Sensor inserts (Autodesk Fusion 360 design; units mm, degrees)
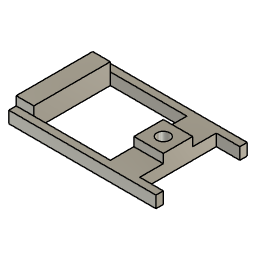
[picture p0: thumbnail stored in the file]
base_mesh_feature "Base Mesh Feature1"
convert_mesh "Convert Mesh1" bodies "DHT22_Case_-_DHT22_Case_Bot"
sketch "Sketch1" plane through (0, 0, 2) normal (0, 0, 1) x axis (-1, 0, 0)
  line L1 (18.25, 7.75) -> (18.25, -7.75)
  line L2 (18.25, -7.75) -> (-18.25, -7.75)
  line L3 (-18.25, -7.75) -> (18.25, -7.75)
  line L4 (-18.25, 7.75) -> (-18.25, -7.75)
  line L5 (18.25, 7.75) -> (-18.25, 7.75)
  line L6 (18.25, -7.75) -> (18.25, 7.75)
  line L7 (18.25, -6.5) -> (-18.25, -6.5)
  line L8 (-18.25, 6.5) -> (18.25, 6.5)
  line L9 (6.75, 7.75) -> (6.75, -7.75)
  line L10 (-14.25, 6.5) -> (-14.25, -6.5)
  line L11 (-9.25, -6.5) -> (-14.25, -6.5)
  line L12 (-9.25, 6.5) -> (-9.25, -6.5)
  line L13 (-14.25, 6.5) -> (-9.25, 6.5)
  line L14 (-14.25, -6.5) -> (-14.25, 6.5)
  line L15 (3.75, -6.5) -> (6.75, -6.5)
  line L16 (3.75, 6.5) -> (3.75, -6.5)
  line L17 (6.75, 6.5) -> (3.75, 6.5)
  line L18 (6.75, -6.5) -> (6.75, 6.5)
  line L19 (-14.25, -7.75) -> (6.75, -7.75)
  line L20 (6.75, -6.5) -> (-14.25, -6.5)
  line L21 (6.75, -7.75) -> (6.75, -6.5)
  line L22 (-14.25, 6.5) -> (6.75, 6.5)
  line L23 (6.75, 7.75) -> (-14.25, 7.75)
  line L24 (6.75, 6.5) -> (6.75, 7.75)
  line L25 (-18.25, -7.75) -> (-14.25, -7.75)
  line L26 (-18.25, -6.5) -> (-18.25, -7.75)
  line L27 (-14.25, -6.5) -> (-18.25, -6.5)
  line L28 (-18.25, 6.5) -> (-14.25, 6.5)
  line L29 (-18.25, 7.75) -> (-18.25, 6.5)
  line L30 (-14.25, 7.75) -> (-18.25, 7.75)
  point P2 (18.25, -7.75)
  point P5 (18.25, -7.75)
  point P9 (-18.25, -6.5)
  point P10 (18.25, -6.5)
  point P11 (18.25, 6.5)
  point P12 (-18.25, 6.5)
  point P13 (6.75, -7.75)
  point P14 (6.75, 7.75)
  point P15 (-14.25, -6.5)
  point P16 (-14.25, 6.5)
  point P20 (6.75, -6.5)
  point P27 (-14.25, 7.75)
  point P6 (-18.25, -7.75)
  point P8 (18.25, 7.75)
  point P4 (-18.25, -7.75)
  point P17 (-9.25, -6.5)
  point P21 (3.75, -6.5)
  horizontal L3
  vertical L4
  horizontal L5
  vertical L6
  coincident P2 P5
  coincident L4 P9
  coincident L6 P10
  perpendicular L6 L7
  coincident L6 P11
  coincident L4 P12
  perpendicular L4 L8
  coincident L3 P13
  coincident L5 P14
  perpendicular L5 L9
  coincident L7 P15
  coincident L8 P16
  perpendicular L8 L10
  horizontal L11
  vertical L12
  horizontal L13
  vertical L14
  horizontal L15
  vertical L16
  horizontal L17
  vertical L18
  coincident L9 P20
  coincident L7 P20
  horizontal L19
  horizontal L20
  vertical L21
  horizontal L22
  horizontal L23
  vertical L24
  coincident L5 P27
  horizontal L25
  vertical L26
  horizontal L27
  horizontal L28
  vertical L29
  horizontal L30
  dimension "d1" distance P5 P6 = 36.5
  dimension "d2" distance P5 P8 = 15.5
  dimension "d5" distance P4 L7 = 1.25
  dimension "d6" distance L5 L8 = 1.25
  dimension "d7" distance L6 L9 = 11.5 (= "36.5 mm - 25 mm")
  dimension "d8" distance L4 L10 = 4
  dimension "d9" distance P15 P17 = 5
  dimension "d10" distance P20 P21 = 3
extrude "Extrude1" new body sketch "Sketch1" profile of L2 L3 L5 L11 L13 L15 L17 L19 L20 L21 L22 L23 L24 along normal blind 2
extrude "Extrude2" add sketch "Sketch1" profile of L11 L12 L13 L14 L15 L16 L17 L18 L20 L22 along normal blind 3.5
sketch "Sketch2" plane through (0, 0, 5.5) normal (0, 0, 1) x axis (-1, 0, 0)
  line L1 (-9.25, 6.5) -> (-9.25, -6.5)
  line L2 (-14.25, 6.5) -> (-9.25, 6.5)
  line L3 (-14.25, -6.5) -> (-14.25, 6.5)
  line L4 (-9.25, -6.5) -> (-14.25, -6.5)
  line L5 (-14.25, 6.5) -> (-9.25, -6.5)
  line L6 (-9.25, 6.5) -> (-14.25, -6.5)
  line L7 (-9.25, -2.5) -> (-14.25, -2.5)
  line L8 (-9.25, 2.5) -> (-9.25, -2.5)
  line L9 (-14.25, 2.5) -> (-9.25, 2.5)
  line L10 (-14.25, -2.5) -> (-14.25, 2.5)
  circle C1 centre (-11.75, 0) radius 1
  point P2 (-9.25, -6.5)
  point P6 (-9.25, -6.5)
  point P4 (-14.25, 6.5)
  point P7 (-14.25, 6.5)
  point P5 (-14.25, -6.5)
  point P8 (-14.25, -6.5)
  point P3 (-9.25, 6.5)
  point P9 (-9.25, 6.5)
  point P10 (-11.75, 0)
  point P11 (-14.25, -2.5)
  point P14 (-14.25, 2.5)
  coincident P2 P6
  coincident P4 P7
  coincident P5 P8
  coincident P3 P9
  midpoint L6 P10
  horizontal L7
  vertical L8
  horizontal L9
  vertical L10
  dimension "d15" diameter C1 = 2
  dimension "d55" distance P11 P14 = 5
hole "Hole1" HoleDepth 4 HoleDiameter 2.2 TipAngle 180
base_mesh_feature "Base Mesh Feature2"
convert_mesh "Convert Mesh2" bodies "MQ2_Case_-_MQ2_Case_Bot"
sketch "Sketch3" plane through (0, 0, 0) normal (0, 0, 1) x axis (1, 0, 0)
  line L1 (17, -42) -> (-17, -42)
  line L2 (17, -64) -> (17, -42)
  line L3 (-17, -64) -> (17, -64)
  line L4 (-17, -42) -> (-17, -64)
  line L5 (17, -43.5) -> (-17, -43.5)
  line L6 (17, -62.5) -> (-17, -62.5)
  line L7 (-14, -64) -> (-14, -42)
  line L8 (12, -43.5) -> (17, -43.5)
  line L9 (12, -47.5) -> (12, -43.5)
  line L10 (17, -47.5) -> (12, -47.5)
  line L11 (17, -43.5) -> (17, -47.5)
  line L12 (12, -62.5) -> (17, -62.5)
  line L13 (12, -58.5) -> (12, -62.5)
  line L14 (17, -58.5) -> (12, -58.5)
  line L15 (17, -62.5) -> (17, -58.5)
  line L16 (-9, -43.5) -> (-14, -43.5)
  line L17 (-9, -47.5) -> (-9, -43.5)
  line L18 (-14, -47.5) -> (-9, -47.5)
  line L19 (-14, -43.5) -> (-14, -47.5)
  line L20 (17, -42) -> (-14, -42)
  line L21 (17, -43.5) -> (17, -42)
  line L22 (-14, -43.5) -> (17, -43.5)
  line L23 (-14, -42) -> (-14, -43.5)
  line L24 (-9, -62.5) -> (-14, -62.5)
  line L25 (-9, -58.5) -> (-9, -62.5)
  line L26 (-14, -58.5) -> (-9, -58.5)
  line L27 (-14, -62.5) -> (-14, -58.5)
  line L28 (-14, -64) -> (17, -64)
  line L29 (-14, -62.5) -> (-14, -64)
  line L30 (17, -62.5) -> (-14, -62.5)
  line L31 (17, -64) -> (17, -62.5)
  line L32 (-12.5, -47.5) -> (-14, -47.5)
  line L33 (-12.5, -58.5) -> (-12.5, -47.5)
  line L34 (-14, -58.5) -> (-12.5, -58.5)
  line L35 (-14, -47.5) -> (-14, -58.5)
  line L36 (15.5, -47.5) -> (17, -47.5)
  line L37 (15.5, -58.5) -> (15.5, -47.5)
  line L38 (17, -58.5) -> (15.5, -58.5)
  line L39 (17, -47.5) -> (17, -58.5)
  point P6 (-17, -43.5)
  point P7 (17, -43.5)
  point P8 (-17, -62.5)
  point P9 (17, -62.5)
  point P10 (-14, -42)
  point P11 (-14, -64)
  point P18 (-14, -43.5)
  point P24 (-14, -62.5)
  point P31 (-12.5, -58.5)
  point P34 (15.5, -58.5)
  point P12 (12, -43.5)
  point P14 (17, -47.5)
  point P15 (12, -62.5)
  point P17 (17, -58.5)
  point P19 (-9, -43.5)
  point P21 (-14, -47.5)
  point P25 (-9, -62.5)
  point P27 (-14, -58.5)
  horizontal L1
  vertical L2
  horizontal L3
  vertical L4
  coincident L4 P6
  coincident L2 P7
  perpendicular L2 L5
  coincident L4 P8
  coincident L2 P9
  perpendicular L4 L6
  coincident L1 P10
  coincident L3 P11
  perpendicular L3 L7
  horizontal L8
  vertical L9
  horizontal L10
  vertical L11
  horizontal L12
  vertical L13
  horizontal L14
  vertical L15
  horizontal L16
  vertical L17
  horizontal L18
  vertical L19
  coincident L5 P18
  coincident L7 P18
  horizontal L20
  vertical L21
  horizontal L22
  vertical L23
  horizontal L24
  vertical L25
  horizontal L26
  vertical L27
  coincident L7 P24
  coincident L6 P24
  horizontal L28
  vertical L29
  horizontal L30
  vertical L31
  horizontal L32
  vertical L33
  horizontal L34
  vertical L35
  coincident L26 P31
  horizontal L36
  vertical L37
  horizontal L38
  vertical L39
  coincident L14 P34
  dimension "d19" distance L1 L5 = 1.5
  dimension "d20" distance L3 L6 = 1.5
  dimension "d21" distance L4 L7 = 3
  dimension "d22" distance P7 P12 = 5
  dimension "d23" distance P7 P14 = 4
  dimension "d24" distance P9 P15 = 5
  dimension "d25" distance P9 P17 = 4
  dimension "d26" distance P18 P19 = 5
  dimension "d27" distance P18 P21 = 4
  dimension "d28" distance P24 P25 = 5
  dimension "d29" distance P24 P27 = 4
extrude "Extrude1" new body sketch "Sketch3" profile of L1 L2 L3 L8 L10 L12 L14 L16 L18 L20 L21 L22 L23 L24 L26 L28 L29 L30 L31 L32 L33 L34 L35 L36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 along normal blind 2
extrude "Extrude2" add sketch "Sketch3" profile of L2 L8 L9 L10 L11 L12 L13 L14 L15 L16 L17 L18 L19 L22 L24 L25 L26 L27 L30 L32 L34 L36 L38 along normal blind 6
sketch "Sketch4" plane through (0, 0, 6) normal (0, 0, 1) x axis (-1, 0, 0)
  line L1 (14, 43.5) -> (9, 43.5)
  line L2 (14, 47.5) -> (14, 43.5)
  line L3 (9, 47.5) -> (14, 47.5)
  line L4 (9, 43.5) -> (9, 47.5)
  line L5 (10, 43.5) -> (14, 43.5)
  line L6 (10, 47.5) -> (10, 43.5)
  line L7 (14, 47.5) -> (10, 47.5)
  line L8 (14, 43.5) -> (14, 47.5)
  line L9 (10, 58.5) -> (14, 58.5)
  line L10 (10, 62.5) -> (10, 58.5)
  line L11 (14, 62.5) -> (10, 62.5)
  line L12 (14, 58.5) -> (14, 62.5)
  line L13 (-13, 43.5) -> (-17, 43.5)
  line L14 (-13, 47.5) -> (-13, 43.5)
  line L15 (-17, 47.5) -> (-13, 47.5)
  line L16 (-17, 43.5) -> (-17, 47.5)
  line L17 (-13, 58.5) -> (-17, 58.5)
  line L18 (-13, 62.5) -> (-13, 58.5)
  line L19 (-17, 62.5) -> (-13, 62.5)
  line L20 (-17, 58.5) -> (-17, 62.5)
  line L21 (10, 47.5) -> (14, 43.5)
  line L22 (10, 43.5) -> (14, 47.5)
  line L23 (-17, 47.5) -> (-13, 43.5)
  line L24 (-17, 43.5) -> (-13, 47.5)
  line L25 (-17, 62.5) -> (-13, 58.5)
  line L26 (-17, 58.5) -> (-13, 62.5)
  line L27 (10, 62.5) -> (14, 58.5)
  line L28 (10, 58.5) -> (14, 62.5)
  circle C1 centre (12, 45.5) radius 1
  circle C2 centre (-15, 45.5) radius 1
  circle C3 centre (12, 60.5) radius 1
  circle C4 centre (-15, 60.5) radius 1
  point P8 (10, 47.5)
  point P3 (14, 43.5)
  point P6 (14, 43.5)
  point P22 (12, 45.5)
  point P23 (-15, 45.5)
  point P24 (12, 60.5)
  point P25 (-15, 60.5)
  horizontal L5
  vertical L6
  horizontal L7
  vertical L8
  coincident L3 P8
  coincident P3 P6
  horizontal L9
  vertical L10
  horizontal L11
  vertical L12
  horizontal L13
  vertical L14
  horizontal L15
  vertical L16
  horizontal L17
  vertical L18
  horizontal L19
  vertical L20
  perpendicular L23 L24
  perpendicular L24 L25
  perpendicular L26 L27
  midpoint L21 P22
  midpoint L23 P23
  midpoint L28 P24
  midpoint L26 P25
  dimension "d35" diameter C1 = 2
  dimension "d36" diameter C2 = 2
  dimension "d37" diameter C3 = 2
  dimension "d38" diameter C4 = 2
hole "Hole1" HoleDepth 4.5 HoleDiameter 2.2 TipAngle 180
sketch "Sketch1" plane through (0, 0, 2) normal (0, 0, 1) x axis (-1, 0, 0)
  line L1 (18.25, 7.75) -> (18.25, -7.75)
  line L2 (18.25, -7.75) -> (-18.25, -7.75)
  line L3 (-18.25, -7.75) -> (18.25, -7.75)
  line L4 (-18.25, 5.25) -> (-18.25, -7.75)
  line L5 (18.25, 5.25) -> (-18.25, 5.25)
  line L6 (18.25, -7.75) -> (18.25, 5.25)
  line L7 (18.25, -6.5) -> (-18.25, -6.5)
  line L8 (-18.25, 4) -> (18.25, 4)
  line L9 (6.75, 5.25) -> (6.75, -7.75)
  line L10 (-14.25, 4) -> (-14.25, -6.5)
  line L11 (-14.25, -7.75) -> (6.75, -7.75)
  line L12 (-14.25, -6.5) -> (-14.25, -7.75)
  line L13 (6.75, -6.5) -> (-14.25, -6.5)
  line L14 (6.75, -7.75) -> (6.75, -6.5)
  line L15 (6.75, 5.25) -> (-14.25, 5.25)
  line L16 (6.75, 6.5) -> (6.75, 5.25)
  line L17 (-18.25, -7.75) -> (6.75, -7.75)
  line L18 (-18.25, -10.25) -> (-18.25, -7.75)
  line L19 (6.75, -10.25) -> (-18.25, -10.25)
  line L20 (6.75, -7.75) -> (6.75, -10.25)
  line L21 (-18.25, 5.25) -> (6.75, 5.25)
  line L22 (-18.25, 7.75) -> (-18.25, 5.25)
  line L23 (6.75, 7.75) -> (-18.25, 7.75)
  line L24 (6.75, 5.25) -> (6.75, 7.75)
  line L25 (-9.25, -7.75) -> (-14.25, -7.75)
  line L26 (-9.25, 5.25) -> (-9.25, -7.75)
  line L27 (-14.25, 5.25) -> (-9.25, 5.25)
  line L28 (-14.25, -7.75) -> (-14.25, 5.25)
  line L29 (3.75, -7.75) -> (6.75, -7.75)
  line L30 (3.75, 5.25) -> (3.75, -7.75)
  line L31 (6.75, 5.25) -> (3.75, 5.25)
  line L32 (6.75, -7.75) -> (6.75, 5.25)
  point P2 (18.25, -7.75)
  point P5 (18.25, -7.75)
  point P9 (-18.25, -6.5)
  point P10 (18.25, -6.5)
  point P11 (18.25, 4)
  point P12 (-18.25, 4)
  point P13 (6.75, -7.75)
  point P14 (6.75, 5.25)
  point P15 (-14.25, -6.5)
  point P16 (-14.25, 4)
  point P20 (-14.25, 5.25)
  point P31 (3.75, 5.25)
  point P6 (-18.25, -7.75)
  point P8 (18.25, 5.25)
  point P4 (-18.25, -7.75)
  point P24 (6.75, -10.25)
  point P27 (6.75, 7.75)
  point P18 (-14.25, -7.75)
  point P28 (-9.25, -7.75)
  point P30 (3.75, -7.75)
  horizontal L3
  vertical L4
  horizontal L5
  vertical L6
  coincident P2 P5
  coincident L4 P9
  coincident L6 P10
  perpendicular L6 L7
  coincident L6 P11
  coincident L4 P12
  perpendicular L4 L8
  coincident L3 P13
  coincident L5 P14
  perpendicular L5 L9
  coincident L7 P15
  coincident L8 P16
  perpendicular L8 L10
  horizontal L11
  vertical L12
  horizontal L13
  vertical L14
  horizontal L15
  vertical L16
  coincident L5 P20
  horizontal L17
  vertical L18
  horizontal L19
  vertical L20
  horizontal L21
  vertical L22
  horizontal L23
  vertical L24
  horizontal L25
  vertical L26
  horizontal L27
  vertical L28
  horizontal L29
  vertical L30
  horizontal L31
  vertical L32
  coincident L15 P31
  dimension "d1_1" distance P5 P6 = 36.5
  dimension "d2_1" distance P5 P8 = 13
  dimension "d5_1" distance P4 L7 = 1.25
  dimension "d6_1" distance L5 L8 = 1.25
  dimension "d7_1" distance L6 L9 = 11.5 (= "36.5 mm - 25 mm")
  dimension "d8_1" distance L4 L10 = 4
  dimension "d42" distance P13 P24 = 2.5
  dimension "d43" distance P14 P27 = 2.5
  dimension "d44" distance P18 P28 = 5
  dimension "d45" distance P13 P30 = 3
extrude "Extrude1" new body sketch "Sketch1" profile of L2 L3 L5 L11 L15 L17 L18 L19 L20 L21 L22 L23 L24 L25 L27 L29 L31 along normal blind 2 named "d11_1"
extrude "Extrude2" add sketch "Sketch1" profile of L2 L3 L5 L11 L12 L13 L14 L15 L17 L21 L25 L26 L27 L28 L29 L30 L31 L32 along normal blind 3.5 named "d13_1"
sketch "Sketch2" plane through (0, 0, 5.5) normal (0, 0, 1) x axis (-1, 0, 0)
  line L1 (-14.25, 5.25) -> (-9.25, -7.75)
  line L2 (-9.25, 5.25) -> (-14.25, -7.75)
  line L3 (-9.25, 5.25) -> (-9.25, -7.75)
  line L4 (6.75, 5.25) -> (6.75, -7.75)
  line L5 (-14.25, -7.75) -> (-14.25, 5.25)
  line L6 (-9.25, -7.75) -> (-14.25, -7.75)
  line L7 (-14.25, 5.25) -> (-9.25, 5.25)
  line L8 (3.75, 5.25) -> (6.75, 5.25)
  line L9 (3.75, -7.75) -> (3.75, 5.25)
  line L10 (6.75, -7.75) -> (3.75, -7.75)
  line L11 (-14.25, -1.25) -> (-11.75, -1.25)
  line L12 (-14.25, -3.75) -> (-14.25, -1.25)
  line L13 (-9.25, -3.75) -> (-14.25, -3.75)
  line L14 (-9.25, 1.25) -> (-9.25, -3.75)
  line L15 (-14.25, 1.25) -> (-9.25, 1.25)
  line L16 (-14.25, -3.75) -> (-14.25, 1.25)
  circle C1 centre (-11.75, -1.25) radius 1
  point P2 (-11.75, -1.25)
  point P3 (-9.25, -7.75)
  point P11 (-9.25, -7.75)
  point P8 (-14.25, -7.75)
  point P12 (-14.25, -7.75)
  point P4 (-9.25, 5.25)
  point P13 (-9.25, 5.25)
  point P7 (-14.25, 5.25)
  point P14 (-14.25, 5.25)
  point P15 (-11.75, -1.25)
  point P16 (-14.25, -1.25)
  point P17 (-14.25, -3.75)
  point P20 (-14.25, 1.25)
  midpoint L2 P2
  coincident P3 P11
  coincident P8 P12
  coincident P4 P13
  coincident P7 P14
  coincident P2 P15
  midpoint L5 P16
  perpendicular L11 L12
  horizontal L13
  vertical L14
  horizontal L15
  vertical L16
  dimension "d15_1" diameter C1 = 2
  dimension "d46" distance P16 P17 = 2.5
  dimension "d47" distance P17 P20 = 5
hole "Hole1" HoleDepth 4 named "d16_1" HoleDiameter 2.2 named "d17_1" TipAngle 180 named "d18_1"
extrude "Extrude4" cut sketch "Sketch2" profile of L3 L5 L6 L7 L13 L15 against normal blind 1.5
extrude "Extrude4" cut sketch "Sketch2" profile of L1 L2 L3 L4 L7 L9 against normal blind 1.5
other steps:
create_component "CreateComponent1"
create_component "CreateComponent2"
create_component "CreateComponent3"
named bodies: "DHT22_Case_-_DHT22_Case_Bot", "MQ2_Case_-_MQ2_Case_Bot"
